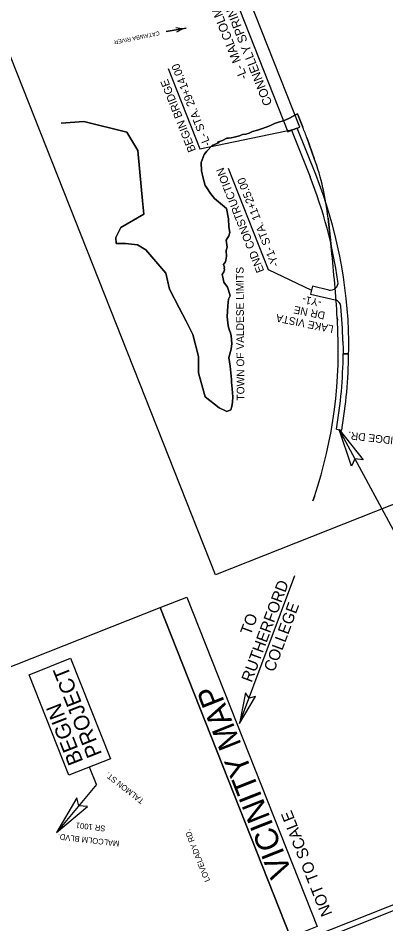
# Model space of a CAD drawing. Extents: x 1247235 to 1260080, y 742320 to 754020.
# Drawn here: x 1250319 to 1251767, y 744667 to 748232 of the extents above; entities that cross this region are included whole.
import ezdxf

# ---------------------------------------------------------------- set-up
doc = ezdxf.new("R2010")
doc.units = 0
for name, color, linetype in [('Default', 7, 'Continuous'), ('Exist Hydro River Flow Arrow CELL', 7, 'Continuous'), ('Exist Hydro Stream or Body of Water Text', 7, 'Continuous'), ('Old_Level_50', 7, 'Continuous'), ('Old_Level_60', 7, 'Continuous'), ('Prop DSN Text', 7, 'Continuous'), ('Prop Grid Mask', 7, 'Continuous'), ('Prop Horizontal Alignment Direction Label', 7, 'Continuous'), ('Prop PHM City or Township Limit Line', 7, 'Continuous'), ('Prop Shade Heavy', 7, 'Continuous'), ('Prop Shade Medium', 7, 'Continuous'), ('Prop Terminator CELL', 7, 'Continuous'), ('Scratch_Level_0', 7, 'Continuous'), ('Scratch_Level_3', 7, 'Continuous'), ('Sheet Data Field CELL', 7, 'Continuous'), ('Sheet Title CELL', 7, 'Continuous')]:
    doc.layers.add(name, color=color, linetype=linetype)

# ---------------------------------------------------------------- blocks, each defined once
blk = doc.blocks.new('EXIST HYDRO RIVER FLOW ARROW')
at = {"layer": 'Default'}
blk.add_line((0, 0), (0, 0), dxfattribs=at)
blk.add_lwpolyline([(0, 0.04575), (0.03775, 0.03), (0.07725, 0.01725), (0.118, 0.00775), (0.159, 0.0015), (0.2, 0), (-0.2, 0), (0.2, 0), (0.159, -0.0015), (0.118, -0.00775), (0.07725, -0.01725), (0.03775, -0.03), (0, -0.04575)], dxfattribs=at)

msp = doc.modelspace()

# ---------------------------------------------------------------- linework, layer by layer
at = {"layer": 'Old_Level_60'}
msp.add_line((1251190.9, 745454.8), (1251408.3, 746038.5), dxfattribs=at)
at = {"layer": 'Prop DSN Text'}
for p, q in [((1250909, 748033.2), (1251034, 747717)), ((1251145.5, 747640.9), (1251303, 747242.5)), ((1250627.5, 745215.4), (1250600.4, 745284)), ((1250627.5, 745215.4), (1250470.4, 745026.8))]:
    msp.add_line(p, q, dxfattribs=at)
for points in [[(1251034, 747717), (1251406.8, 747794.5)], [(1251303, 747242.5), (1251473.7, 747161)]]:
    msp.add_lwpolyline(points, dxfattribs=at)
at = {"layer": 'Prop Grid Mask'}
msp.add_lwpolyline([(1250518.4, 745251.5), (1250361.9, 745647.4), (1250525.8, 745712.3), (1250682.3, 745316.4)], close=True, dxfattribs=at)
at = {"layer": 'Prop Horizontal Alignment Direction Label'}
msp.add_line((1251848.4, 746119.2), (1251582.4, 746612.2), dxfattribs=at)
at = {"layer": 'Prop PHM City or Township Limit Line'}
for p, q in [((1251484.6, 747679.6), (1251456.3, 747758.4)), ((1251456.3, 747758.4), (1251484.6, 747679.6)), ((1251552.3, 747320.2), (1251538.8, 747444.4)), ((1251538.8, 747444.4), (1251552.3, 747320.2)), ((1251575.8, 747042.6), (1251575.2, 747052)), ((1251575.2, 747052), (1251575.8, 747042.6)), ((1251479.5, 746331.2), (1251485.5, 746349.2)), ((1251485.5, 746349.2), (1251479.5, 746331.2))]:
    msp.add_line(p, q, dxfattribs=at)
msp.add_lwpolyline([(1251440, 747801.8), (1251418.7, 747855.5), (1251407.8, 747849.9), (1251387.4, 747837.9), (1251363.6, 747827.1), (1251343.3, 747822.3), (1251328.4, 747816.7), (1251311.8, 747808.5), (1251294.8, 747802.4), (1251276.5, 747795.7), (1251260.9, 747790.5), (1251241, 747785.2), (1251228.5, 747778.5), (1251224.2, 747777.9), (1251215.3, 747775.1), (1251202, 747774.2), (1251190.4, 747768.6), (1251170, 747763.6), (1251158, 747760.9), (1251147.4, 747759.5), (1251140.4, 747758.6), (1251123.6, 747750), (1251107.4, 747744.9), (1251103.3, 747743.9), (1251110, 747741.5), (1251083, 747730), (1251061.7, 747707.5), (1251050.7, 747694.2), (1251040.1, 747663.8), (1251040.7, 747631.2), (1251046.9, 747602), (1251055.2, 747573.2), (1251061.5, 747563.8), (1251076.8, 747541.3), (1251091.4, 747521.8), (1251139.8, 747482.5), (1251147.2, 747441.7), (1251147.8, 747409.8), (1251152.9, 747388.4), (1251148.7, 747374.9), (1251137.9, 747358), (1251142, 747329.8), (1251137.9, 747317.2), (1251139.8, 747293), (1251135.1, 747271.9), (1251127, 747261.7), (1251131.3, 747251.3), (1251130, 747247.2), (1251131, 747241), (1251128.3, 747232.4), (1251122.7, 747222.5), (1251124.2, 747212.4), (1251128.8, 747192.7), (1251143.2, 747172.9), (1251146.6, 747161.3), (1251153.4, 747138), (1251146.8, 747125.7), (1251144.3, 747099.8), (1251141.2, 747055.6), (1251145.7, 747019.9), (1251150.8, 747001.6), (1251155.3, 746992.4), (1251157.6, 746980.5), (1251160.7, 746951.4), (1251157, 746928.1), (1251148.2, 746896.1), (1251153.9, 746861.7), (1251158.5, 746809.4), (1251159.4, 746798.9), (1251161.6, 746772.4), (1251163.7, 746741.3), (1251163.4, 746720.2), (1251160.5, 746702.4), (1251156.5, 746690), (1251140.9, 746683.5), (1251132.1, 746686.9), (1251110.6, 746697.7), (1251055.1, 746741.3), (1251039.3, 746797.8), (1251028.6, 746836), (1251028.6, 746899.7), (1251007.3, 746986.3), (1250980.1, 747038.8), (1250952.9, 747091.3), (1250914.7, 747165), (1250900.8, 747228), (1250844.7, 747292.6), (1250821.7, 747319), (1250788.8, 747339.3), (1250741.7, 747344.5), (1250719.9, 747344.1), (1250704.6, 747343.9), (1250704.2, 747368.2), (1250722.7, 747407.2), (1250814.3, 747459.6), (1250809.2, 747513), (1250798.5, 747624.7), (1250790.3, 747710.9), (1250747.3, 747782.7), (1250578.2, 747824.5), (1250488.9, 747817.6), (1250578.2, 747824.5), (1250747.3, 747782.7), (1250790.3, 747710.9), (1250798.5, 747624.7), (1250809.2, 747513), (1250814.3, 747459.6), (1250722.7, 747407.2), (1250704.2, 747368.2), (1250704.6, 747343.9), (1250719.9, 747344.1), (1250741.7, 747344.5), (1250788.8, 747339.3), (1250821.7, 747319), (1250844.7, 747292.6), (1250900.8, 747228), (1250914.7, 747165), (1250952.9, 747091.3), (1250980.1, 747038.8), (1251007.3, 746986.3), (1251028.6, 746899.7), (1251028.6, 746836), (1251039.3, 746797.8), (1251055.1, 746741.3), (1251110.6, 746697.7), (1251132.1, 746686.9), (1251140.9, 746683.5), (1251156.5, 746690), (1251160.5, 746702.4), (1251163.4, 746720.2), (1251163.7, 746741.3), (1251161.6, 746772.4), (1251159.4, 746798.9), (1251158.5, 746809.4), (1251153.9, 746861.7), (1251148.2, 746896.1), (1251157, 746928.1), (1251160.7, 746951.4), (1251157.6, 746980.5), (1251155.3, 746992.4), (1251150.8, 747001.6), (1251145.7, 747019.9), (1251141.2, 747055.6), (1251144.3, 747099.8), (1251146.8, 747125.7), (1251153.4, 747138), (1251146.6, 747161.3), (1251143.2, 747172.9), (1251128.8, 747192.7), (1251124.2, 747212.4), (1251122.7, 747222.5), (1251128.3, 747232.4), (1251131, 747241), (1251130, 747247.2), (1251131.3, 747251.3), (1251127, 747261.7), (1251135.1, 747271.9), (1251139.8, 747293), (1251137.9, 747317.2), (1251142, 747329.8), (1251137.9, 747358), (1251148.7, 747374.9), (1251152.9, 747388.4), (1251147.8, 747409.8), (1251147.2, 747441.7), (1251139.8, 747482.5), (1251091.4, 747521.8), (1251076.8, 747541.3), (1251061.5, 747563.8), (1251055.2, 747573.2), (1251046.9, 747602), (1251040.7, 747631.2), (1251040.1, 747663.8), (1251050.7, 747694.2), (1251061.7, 747707.5), (1251083, 747730), (1251110, 747741.5), (1251103.3, 747743.9), (1251107.4, 747744.9), (1251123.6, 747750), (1251140.4, 747758.6), (1251147.4, 747759.5), (1251158, 747760.9), (1251170, 747763.6), (1251190.4, 747768.6), (1251202, 747774.2), (1251215.3, 747775.1), (1251224.2, 747777.9), (1251228.5, 747778.5), (1251241, 747785.2), (1251260.9, 747790.5), (1251276.5, 747795.7), (1251294.8, 747802.4), (1251311.8, 747808.5), (1251328.4, 747816.7), (1251343.3, 747822.3), (1251363.6, 747827.1), (1251387.4, 747837.9), (1251407.8, 747849.9), (1251418.7, 747855.5), (1251440, 747801.8)], dxfattribs=at)
for centre, radius, start, end in [((1250073, 747261.2), 1470, 19.7682, 21.5743), ((1250073, 747261.2), 1470, 19.7682, 21.5743), ((1250524.8, 747334.6), 1020, 6.1796, 19.7682), ((1250524.8, 747334.6), 1020, 6.1796, 19.7682), ((1245617, 746677.6), 5970, 3.59601, 6.17962), ((1245617, 746677.6), 5970, 3.59601, 6.17962), ((1249749.4, 746927.8), 1830, 341.568, 3.596), ((1249749.4, 746927.8), 1830, 341.568, 3.596)]:
    msp.add_arc(centre, radius, start, end, dxfattribs=at)
at = {"layer": 'Prop Shade Heavy'}
for p, q in [((1250984.8, 748785.7), (1251380.8, 747784.2)), ((1251428.2, 747803), (1251032.2, 748804.5)), ((1251418, 747798.9), (1251428.2, 747803))]:
    msp.add_line(p, q, dxfattribs=at)
msp.add_lwpolyline([(1251380.8, 747784.2), (1251395.7, 747790.1), (1251418, 747798.9)], dxfattribs=at)
at = {"layer": 'Prop Shade Medium'}
for p, q in [((1251418, 747798.9), (1251395.7, 747790.1)), ((1251395.7, 747790.1), (1251467.9, 747607.3)), ((1251490.3, 747616.2), (1251418, 747798.9)), ((1251477.4, 747176.6), (1251470, 747145.4)), ((1251541.4, 747161.4), (1251477.4, 747176.6)), ((1251470, 747145.4), (1251566.8, 747122.5)), ((1251609.3, 746910.7), (1251598.6, 746910.8)), ((1251598.7, 746910.8), (1251609.3, 746910.7)), ((1251609.3, 746910.7), (1251619.8, 746910.6)), ((1251619.8, 746910.6), (1251609.3, 746910.7)), ((1251571.9, 746614), (1251592.8, 746610.5))]:
    msp.add_line(p, q, dxfattribs=at)
for points in [[(1251619.8, 746910.6), (1251620, 746915.6), (1251620.2, 746920.7), (1251620.4, 746925.7), (1251620.5, 746930.7), (1251620.6, 746935.8), (1251620.8, 746940.8), (1251620.9, 746945.8), (1251621, 746950.8), (1251621, 746955.9), (1251621.1, 746960.9)], [(1251597.1, 746960.5), (1251597.3, 746955.5), (1251597.5, 746950.5), (1251597.7, 746945.6), (1251597.9, 746940.6), (1251598.1, 746935.6), (1251598.2, 746930.7), (1251598.3, 746925.7), (1251598.5, 746920.7), (1251598.6, 746915.8), (1251598.7, 746910.8)]]:
    msp.add_lwpolyline(points, dxfattribs=at)
for centre, radius, start, end in [((1249749.4, 746927.8), 1848, 8.3105, 21.5743), ((1249749.4, 746927.8), 1872, 1.0129, 21.5743), ((1251548.3, 747190.6), 30, 256.647, 8.3105), ((1251559.9, 747093.3), 30, 5.2222, 76.647), ((1249749.4, 746927.8), 1848, 1.0129, 5.2222), ((1249749.4, 746927.8), 1849.3, 350.2314, 359.4727), ((1249749.4, 746927.8), 1870.5, 350.2314, 359.4727)]:
    msp.add_arc(centre, radius, start, end, dxfattribs=at)
at = {"layer": 'Prop Terminator CELL'}
for points in [[(1251630.8, 746468.5), (1251582.4, 746612.2), (1251677.2, 746492.6), (1251644.7, 746496.8)], [(1251213.7, 745575.9), (1251190.9, 745454.8), (1251253.8, 745561.7), (1251228.1, 745554.7)], [(1250550, 745163.4), (1250470.4, 745026.8), (1250592.3, 745129), (1250558.3, 745131.6)]]:
    msp.add_lwpolyline(points, close=True, dxfattribs=at)
at = {"layer": 'Scratch_Level_0'}
msp.add_lwpolyline([(1249947.5, 744043.6), (1249434.6, 745340.9), (1250878.3, 745911.7), (1251391.3, 744614.5)], close=True, dxfattribs=at)
at = {"layer": 'Scratch_Level_3'}
msp.add_lwpolyline([(1251095.3, 746040.1), (1249533.8, 749989.2), (1251115.9, 750614.8), (1252677.6, 746665.7)], close=True, dxfattribs=at)
at = {"layer": 'Sheet Title CELL'}
for p, q in [((1254098, 745628), (1249829.6, 743940.2)), ((1253315.5, 745342.8), (1249821.3, 743961.2))]:
    msp.add_line(p, q, dxfattribs=at)
for points in [[(1251391.3, 744614.5), (1250878.3, 745911.7), (1250982.9, 745953.1), (1251495.9, 744655.8)], [(1249947.5, 744043.6), (1249434.6, 745340.9), (1250878.3, 745911.7), (1251391.3, 744614.5)]]:
    msp.add_lwpolyline(points, close=True, dxfattribs=at)

# ---------------------------------------------------------------- block references
at = {"layer": 'Exist Hydro River Flow Arrow CELL', "xscale": 200.00000000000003, "yscale": 200, "rotation": 9.926265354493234}
msp.add_blockref('EXIST HYDRO RIVER FLOW ARROW', (1250941.3, 748185.5), dxfattribs=at)

# ---------------------------------------------------------------- texts
at = {"layer": 'Exist Hydro Stream or Body of Water Text'}
msp.add_text('CATAWBA RIVER', height=16, rotation=191.6597, dxfattribs=at).set_placement((1250874.3, 748180.5))
at = {"layer": 'Old_Level_50'}
msp.add_text('NOT TO SCALE', height=45, rotation=111.5743, dxfattribs=at).set_placement((1251556.5, 744706.7))
at = {"layer": 'Prop DSN Text'}
for s, height, rotation, p in [('CONNELLY SPRINGS RD. (SR 1001)', 35, 111.5755, (1251320.1, 747895)), ('-L- MALCOLM BLVD. /', 35, 111.5755, (1251223.1, 747997.6)), ('-L- STA. 29+14.00', 31.5, 111.5743, (1251077.9, 747734.5)), ('BEGIN BRIDGE', 31.5, 111.5743, (1251019.3, 747711.4)), ('END CONSTRUCTION', 31.5, 111.5743, (1251288.3, 747236.9)), ('-Y1- STA. 11+25.00', 31.5, 111.5743, (1251346.9, 747260.1)), ('TOWN OF VALDESE LIMITS', 30, 90.379, (1251209.8, 746726.4)), ('-Y1-', 30, 168.4735, (1251515.2, 747124.1)), ('DR NE', 30, 168.4735, (1251529.4, 747074.5)), ('LAKE VISTA', 30, 168.4735, (1251562.8, 747021)), ('HARBOR RIDGE DR.', 30, 173.4466, (1252007, 746559.7)), ('RUTHERFORD', 45, 69.5679, (1251238.3, 745614.3)), ('COLLEGE', 45, 69.5679, (1251326.9, 745655.5)), ('TO ', 45, 69.5679, (1251234.1, 745799.7)), ('PROJECT', 60.61, 111.5743, (1250650.2, 745335.3)), ('BEGIN   ', 60.61, 111.5743, (1250576.3, 745306.1))]:
    msp.add_text(s, height=height, rotation=rotation, dxfattribs=at).set_placement(p)
at = {"layer": 'Sheet Data Field CELL'}
for s, height, rotation, p in [('VICINITY MAP', 90, 111.5743, (1251398.5, 744868.8)), ('TALMON ST.', 22.5, 142.0273, (1250816.8, 745154.4)), ('SR 1001', 22.5, 173.3771, (1250663.8, 745052.5)), ('LOVELADY RD.', 22.5, 111.3653, (1251074.9, 744837.2)), ('MALCOLM BLVD.', 22.5, 173.3771, (1250718.5, 744993.2))]:
    msp.add_text(s, height=height, rotation=rotation, dxfattribs=at).set_placement(p)

doc.saveas('drawing.dxf')
